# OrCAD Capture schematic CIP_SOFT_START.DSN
size A; title: Capture Walkthrough; rev: A; company: EMA Design Automation; note: EMA-12345678; note: 225 Tech Park Dr; note: Rochester, NY
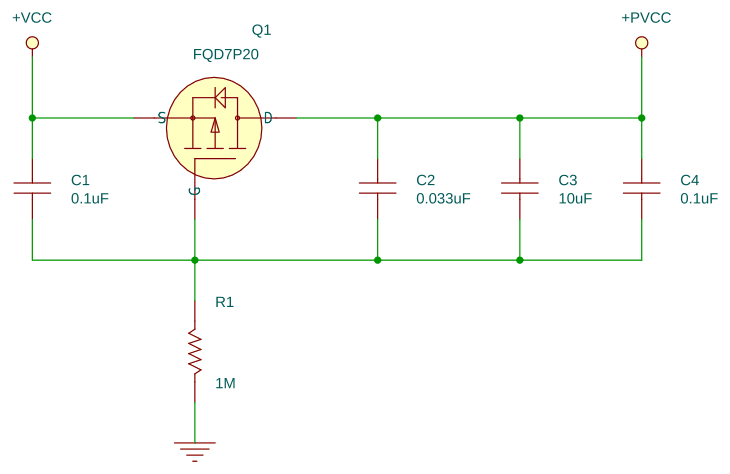
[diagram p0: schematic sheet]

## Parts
C1  0.1uF  [SMC0603]
C2  0.033uF  [SMC0603]
C3  10uF  [CAPC3225X279N]
C4  0.1uF  [SMC0603]
Q1  FQD7P20  [TO230P950X240-3N]
R1  1M  [SMR0603]

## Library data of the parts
C1 C4 = CAP: CAP, Ceramic, SMD, 0.1 uF, 10 %, 25 V, 0603; CLASS: DISCRETE; Dielectric Type: Ceramic; Manufacturer: Kemet; Manufacturer PN: C0603C104K3RAC; PART_NUMBER: EMA-00000135V22; PSpiceTemplate: C^@REFDES %1 %2 C^@REFDES 0.1uF \n.model C^@REFDES CAP C=1 DEV=0.1; Package Size: 0603; Part Type: EMA\Ceramic\SMD\0603; Rated Voltage: 25 V; Temperature Coefficient: X7R; Tolerance: 10%
C2 = CAP: CAP, Ceramic, SMD, 0.033 uF, 10 %, 50 V, 0603; CLASS: DISCRETE; Dielectric Type: Ceramic; Manufacturer: AVX; Manufacturer PN: 06035C333KAT2A; PART_NUMBER: EMA-00000392V22; PSpiceTemplate: C^@REFDES %1 %2 C^@REFDES 0.033uF \n.model C^@REFDES CAP C=1 DEV=0.1; Package Size: 0603; Part Type: EMA\Ceramic\SMD\0603; Rated Voltage: 50 V; Temperature Coefficient: X7R; Tolerance: 10%
C3 = CAP: CAP, Ceramic, SMD, 10 uF, 10 %, 16 V, 1210; CLASS: DISCRETE; Dielectric Type: Ceramic; Manufacturer: AVX; Manufacturer PN: 1210YD106KAT2A; PART_NUMBER: EMA-00000466; PSpiceTemplate: C^@REFDES %1 %2 C^@REFDES 10uF \n.model C^@REFDES CAP C=1 DEV=0.1; Package Size: 1210; Part Type: EMA\Ceramic\SMD\1210; Rated Voltage: 16 V; Temperature Coefficient: X5R; Tolerance: 10%
Q1 = MOSFET_I_EP_GSD: XSTR, MOSFET, P-Channel, FQD7P20, -200 V, -5.7 A, SMD; CLASS: DISCRETE; Manufacturer: Fairchild Semiconductor; Manufacturer PN: FQD7P20TF; PART_NUMBER: EMA-00004861; Package Size: TO-252/DPAK; Part Type: EMA\MOSFET\SMD; Polarity: P-Channel; Rated Power: 2.5 W
R1 = RES: RES, Thick Film, 1M, 1%, 1/10W, SMD, 0603; CLASS: DISCRETE; Manufacturer: Yageo; Manufacturer PN: RC0603FR-071ML; PART_NUMBER: EMA-00007499V42; PSpiceTemplate: R^@REFDES %1 %2 R^@REFDES =1M \n.model R^@REFDES RES R=1 DEV=0.01 TC1=100u; Package Size: 0603; Part Type: EMA\SMD\Thick Film\0603; Rated Power: 1/10W; Temperature Coefficient: +/-100 ppm; Tolerance: 1%

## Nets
+PVCC: C2.1 C3.1 C4.1 Q1.3(D)
+VCC: C1.1 Q1.2(S)
GND: R1.2
N00152: C1.2 C2.2 C3.2 C4.2 Q1.1(G) R1.1
